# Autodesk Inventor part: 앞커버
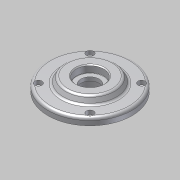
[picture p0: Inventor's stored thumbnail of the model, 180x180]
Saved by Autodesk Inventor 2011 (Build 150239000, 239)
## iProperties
Created: 2013-02
Part Number: 앞커버
Document SubType Name: Modeling
Designer: 한국산업디자인학원[gmhk.co.kr]
Density: 1 g/cm^3
Author: 한국산업디자인학원[gmhk.co.kr]
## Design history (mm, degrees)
sketch "스케치1"
  geometry: C1 r 30 at (0, 0) reference; C2 r 46 at (0, 0); A1 r 91.05 centre (0, -48.55) between (34.185, 35.839) and (-34.185, 35.839) reference; A2 r 91.05 centre (48.55, 0) between (-35.839, 34.185) and (-35.839, -34.185) reference; A3 r 3 centre (-33.058, 33.058) between (-34.185, 35.839) and (-35.839, 34.185) reference; A4 r 3 centre (33.058, 33.058) between (35.839, 34.185) and (34.185, 35.839) reference; A5 r 91.05 centre (-48.55, 0) between (35.839, -34.185) and (35.839, 34.185) reference; A6 r 3 centre (33.058, -33.058) between (34.185, -35.839) and (35.839, -34.185) reference; A7 r 91.05 centre (0, 48.55) between (-34.185, -35.839) and (34.185, -35.839) reference; A8 r 3 centre (-33.058, -33.058) between (-35.839, -34.185) and (-34.185, -35.839) reference; 1 further point
  constraints: 1 centre point, 1 coincident
  dimensions: "d37" = 92 diameter of C2
  node "참조1"
  node "참조2"
  node "참조3"
  node "참조4"
  node "참조5"
  node "참조6"
  node "참조7"
  node "참조8"
  node "참조9"
extrude "돌출1" new body sketch "스케치1" distance "d0" = 8; taper "d1" = 0 deg
sketch "스케치2"
  geometry: C1 r 30 at (0, 0); 1 further point
  constraints: 1 centre point, 1 coincident
  dimensions: "d2" = 60 diameter of C1
extrude "돌출2" join sketch "스케치2" distance "d3" = 7; taper "d4" = -30 deg
hole "구멍1" diameter "d7" = 20; stored, may be unused: countersink angle "d11" = 90 deg, drill point angle "d13" = 118 deg; dims "d5" = 10, "d6" = 10, "d8" = 6, "d9" = 30, "d10" = 8, "d12" = 20
sketch "스케치3"
  geometry: C1 r 1.621 at (28.284, 28.284) reference; C2 r 1.621 at (-28.284, 28.284) reference; C3 r 1.621 at (-28.284, -28.284) reference; C4 r 1.621 at (28.284, -28.284) reference; 1 further point
hole "구멍2" sketch "스케치3" at (28.284, 28.284), (28.284, -28.284), (-28.284, -28.284), (-28.284, 28.284) diameter "d14" = 4.5; stored, may be unused: countersink angle "d18" = 90 deg, drill point angle "d20" = 118 deg; dims "d15" = 6, "d16" = 8, "d17" = 4.4, "d19" = 20
extrude "돌출3" join sketch "스케치1" distance "d21" = 12; taper "d22" = 0 deg
hole "구멍3" diameter "d25" = 30; stored, may be unused: countersink angle "d29" = 90 deg, drill point angle "d31" = 0 deg; dims "d23" = 10, "d24" = 10, "d26" = 6, "d27" = 40, "d28" = 12, "d30" = 15
fillet "모깎기1" dims "d32" = 3, "d33" = 0.3
chamfer "모따기1" distance "d34" = 1; stored, may be unused: second distance "d35" = 2, angle "d36" = 45 deg
fillet "모깎기2" dims "d38" = 3
node "솔리드1"
node "참조10"
node "참조11"
node "참조12"
node "참조13"
